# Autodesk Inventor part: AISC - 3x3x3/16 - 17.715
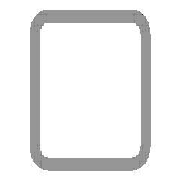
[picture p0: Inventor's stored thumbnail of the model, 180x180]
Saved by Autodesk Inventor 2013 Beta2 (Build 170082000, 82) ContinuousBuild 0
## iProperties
IsCustomPart: 1
Created: 2011-01
Part Number: AISC - 3x3x3/16 - 17.715
Material: Steel, Mild
Description: Tube
Document SubType Name: Modeling
Standard: ANSI
Designer: Beta-8540w
Standards Organization: ANSI
Language: en-US
Size Designation: 3x3x3/16
Categories: <MemberInstance><Categories><Category DisplayName="Structural Shapes" InternalName="089c4875-fa83-4c05-b084-43b9cc11f5ed" Mnemonic="GRDR"><CategoryParameter Dis
Stock Number: 3x3x3/16
Density: 7.86 g/cm^3
_CCFamilyMember: 9
_CCFamilyDisplayName: ANSI AISC (Square) - Tube
_FrameMemberDoc: Frame Member File
_Version: 15.0.0
_GetPNFromCC: 1
G_L: 17.715 in
G_W: 3.000 in
G_H: 3.000 in
Author: Beta-8540w
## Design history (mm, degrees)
node "Start plane"
node "End plane"
sketch "Sketch"
  geometry: L1 (-38.1, -28.575)-(-38.1, 28.575); L2 (-28.575, 38.1)-(28.575, 38.1); L3 (38.1, 28.575)-(38.1, -28.575); L4 (28.575, -38.1)-(-28.575, -38.1); L5 (-28.575, 33.337)-(28.575, 33.338); L6 (33.338, 28.575)-(33.338, -28.575); L7 (28.575, -33.337)-(-28.575, -33.338); L8 (-33.338, -28.575)-(-33.338, 28.575); L9 (0, 56.102)-(0, -56.102) reference; L10 (-56.102, 0)-(56.102, 0) reference; A1 r 9.525 centre (-28.575, -28.575) between (-38.1, -28.575) and (-28.575, -38.1); A2 r 9.525 centre (-28.575, 28.575) between (-28.575, 38.1) and (-38.1, 28.575); A3 r 9.525 centre (28.575, 28.575) between (38.1, 28.575) and (28.575, 38.1); A4 r 9.525 centre (28.575, -28.575) between (28.575, -38.1) and (38.1, -28.575); A5 r 4.763 centre (-28.575, 28.575) between (-28.575, 33.337) and (-33.338, 28.575); A6 r 4.763 centre (28.575, 28.575) between (33.338, 28.575) and (28.575, 33.338); A7 r 4.763 centre (28.575, -28.575) between (28.575, -33.337) and (33.338, -28.575); A8 r 4.763 centre (-28.575, -28.575) between (-33.338, -28.575) and (-28.575, -33.338)
  constraints: 16 end point, 16 point on circle, 8 centre point, 8 tangent, 4 parallel, 3 equal radius, 2 perpendicular, 7 other
  dimensions: "d10" = 76.2 distance between parallel lines of L2 L4 (= G_H); "d11" = 76.2 distance between parallel lines of L1 L3 (= G_W); "d12" = 4.7625 distance between parallel lines of L3 L6 (= G_T); "d15" = 38.1 distance between parallel lines of L2 L10 (= 0.5 x d10); "d16" = 38.1 distance between parallel lines of L9 L3 (= 0.5 x d11); "d17" = 9.525 radius of A1 (= G_IR)
extrude "Body" new body sketch "Sketch" stored distance "d3" = 449.97309 (= G_L); taper "d4" = 0 deg
node "Driven Length"
  sketch "Sketch3"
    geometry: L1 (0, 0)-(10, 0) reference
    constraints: 2 end point, 1 horizontal
  workplane "Work Plane3"
  sketch "Sketch4"
    geometry: L1 (-2, 0)-(12, 0) reference; L2 (-2, 449.973)-(12, 449.973) reference
    dimensions: "d19" = 449.97309 distance between parallel lines of L1 L2 (derived)
body "Solid1"
other parameters: "G_W" = 76.2 [user parameter; used in 1 equation term], "G_H" = 76.2 [user parameter; used in 1 equation term], "G_T" = 4.7625 [user parameter; used in 1 equation term], "G_IR" = 9.525 [user parameter; used in 1 equation term], "G_L" = 449.97309 (= d19) [user parameter; used in 1 equation term], "G_OFFSET_START" = 0 [user parameter; used in 1 equation term], "G_OFFSET_END" = 0 [user parameter; used in 1 equation term], "d13" = 0 (computed from G_OFFSET_START), "d14" = 449.97309 (= G_OFFSET_END + B_L), "B_L" = 449.97309 [user parameter; used in 1 equation term], "d18" = 90 deg
